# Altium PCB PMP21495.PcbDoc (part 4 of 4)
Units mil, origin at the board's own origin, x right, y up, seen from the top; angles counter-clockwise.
Board outline 10700 x 5800 mil, 6 copper layers (Top Layer, Signal Layer 3, Signal Layer 1, Signal Layer 2, Signal Layer 4, Bottom Layer), stack 66 mil thick; 305 components, 138 nets, 864 pads, 367 vias.
Unrouted connection lines stored in the file: 2.
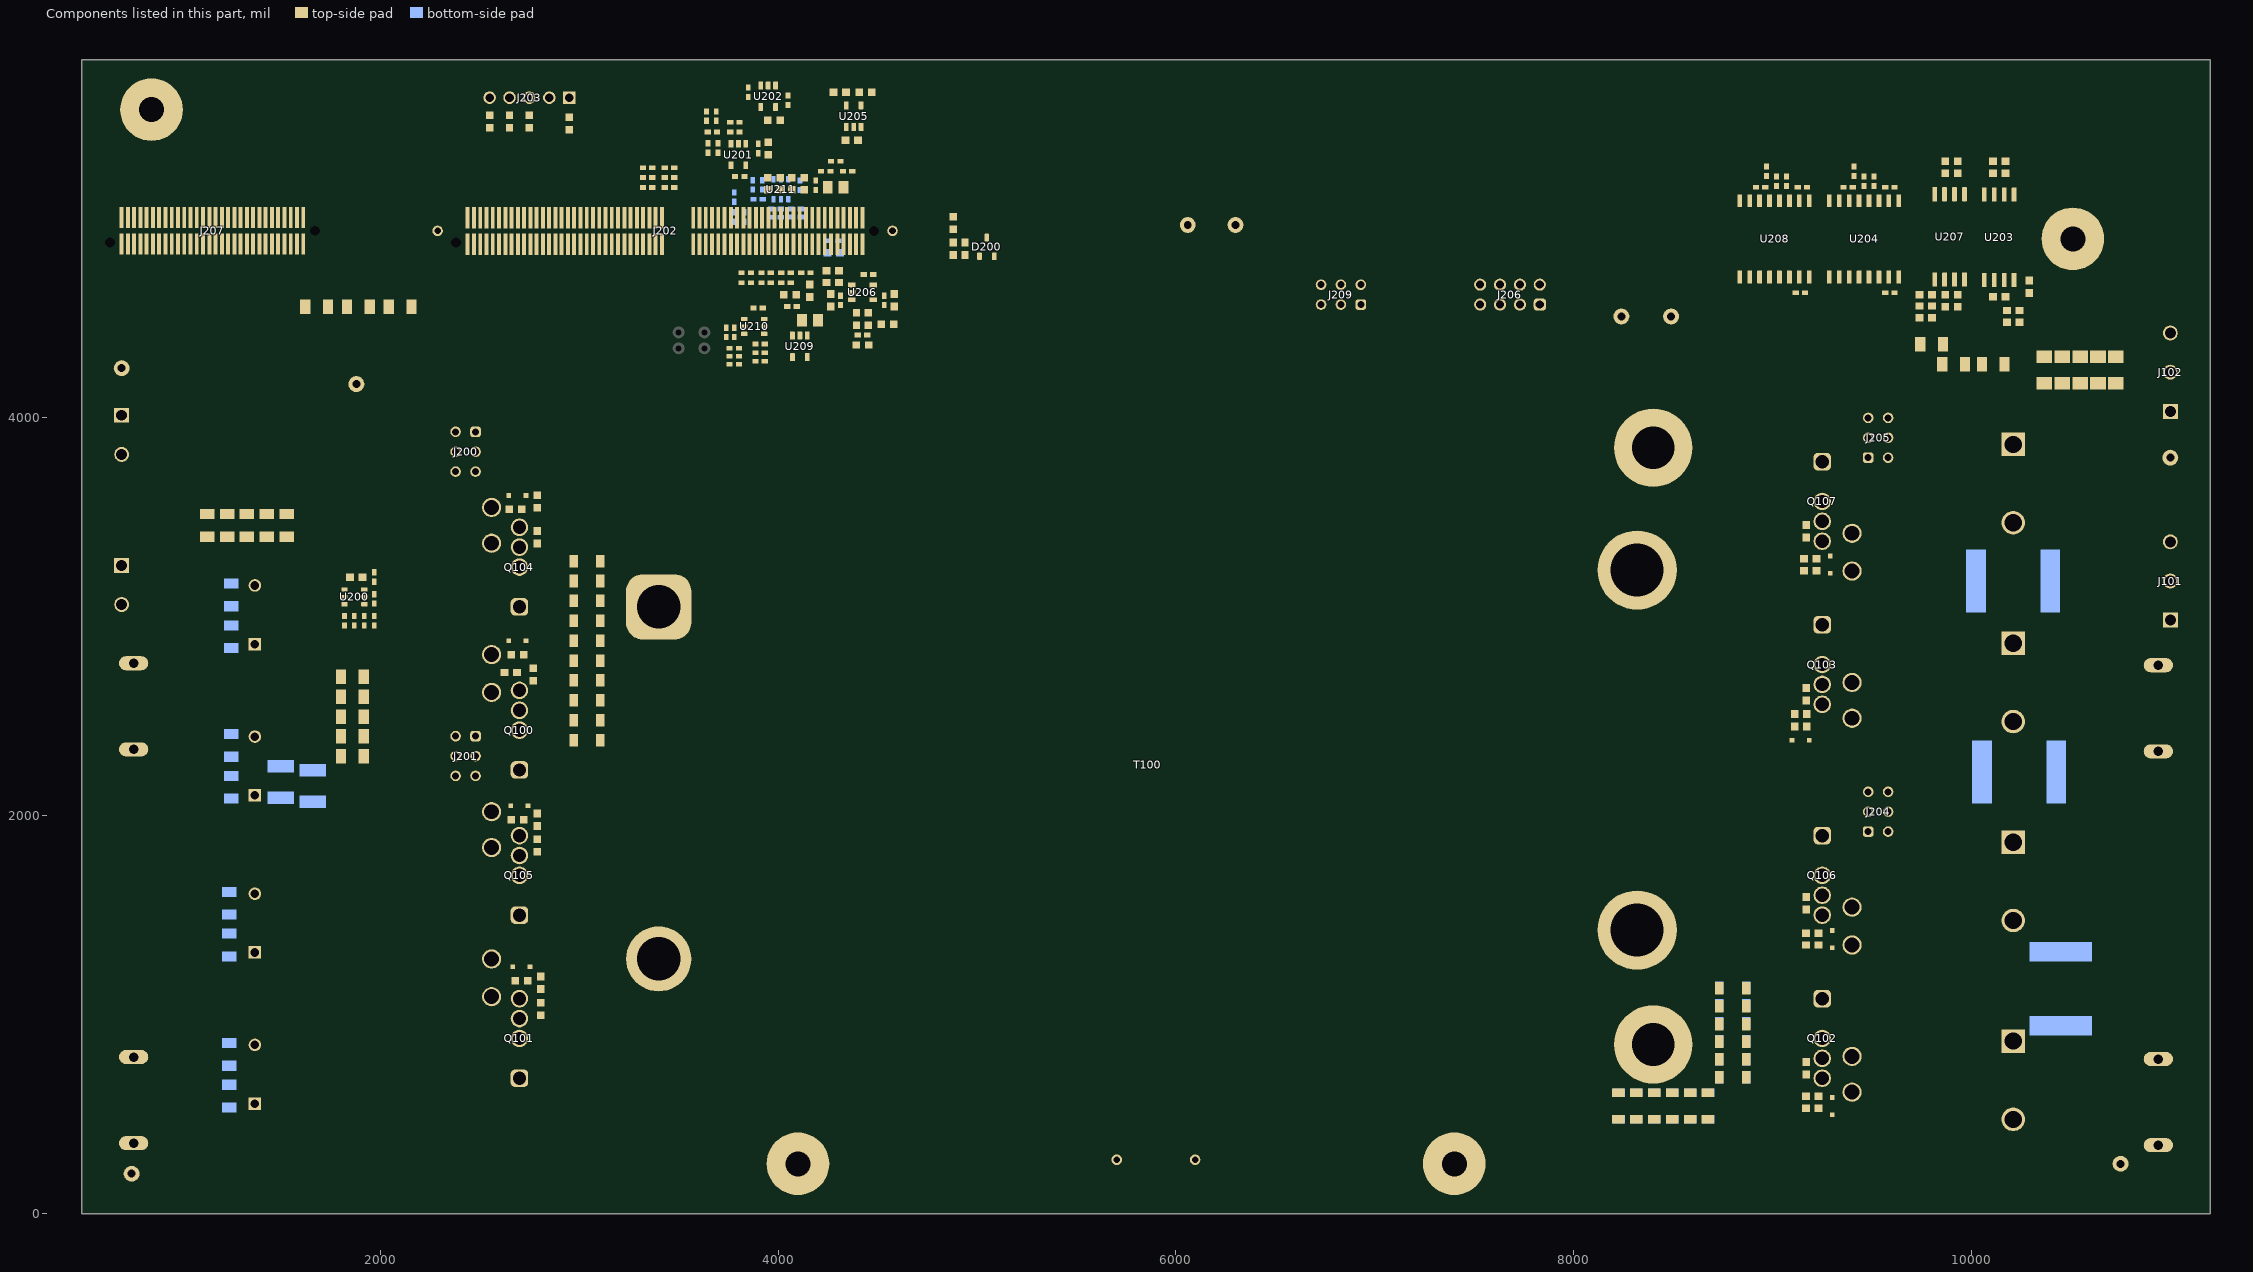
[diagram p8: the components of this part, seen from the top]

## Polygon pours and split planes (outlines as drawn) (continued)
SGND on Signal Layer 2 "SGND" (solid, pour order 309): 6090,500 6070,480 6070,30 6090,10 6340,10 10480,10 10500,30 10500,390 10310,580 9560,580 9560,500
PGND on Signal Layer 2 "PGND" (solid, pour order 320): 22 vertices, not listed, extent 510,2140 11190,5790
NetC100_2 on Signal Layer 3 "C100_2" (solid, pour order 342): 8120,580 8100,600 8100,1120 8648.66,1120 8648.66,1190 8742.6,1190 8760,1172.6 8760,620 8720,580
NetJ105_1 on Signal Layer 3 "J105_1" (solid, pour order 330): 19 vertices, not listed, extent 8100,2720 9320,4060
PGND on Signal Layer 3 "PGND" (solid, pour order 297): 1830,1910 2320,1420 2320,1090 2910,500 5710,500 5730,480 5730,30 5710,10 1610,10 1480,140 1480,1910
PGND on Signal Layer 3 "PGND" (solid, pour order 293): 1080,3430 1020,3370 1020,3340 1020,1560 1070,1510 1470,1510 1830,1870 1830,2850 1590,3090 1590,3410 1570,3430
PGND on Signal Layer 3 "PGND" (solid, pour order 286): 22 vertices, not listed, extent 510,2140 11190,5790
BATT_RTN on Signal Layer 3 "BATT_RTN" (solid, pour order 283): 10320,4270 10300,4290 10300,4450 10410,4560 11170,4560 11190,4540 11190,3960 11170,3940 10961.89,3940 10810,4091.89 10810,4220 10760,4270
VBATT on Signal Layer 3 "VBATT" (solid, pour order 279): 11020,2230 11070,2280 11070,3440 11040,3470 10920,3470 10760,3310 10760,2280 10810,2230
VBUS on Signal Layer 3 "VBUS" (solid, pour order 272): 620,3310 650,3340 860,3340 890,3310 890,2780 890,2320 860,2290 650,2290 620,2320
NetC100_1 on Signal Layer 3 "C100_1" (solid, pour order 263): 29 vertices, not listed, extent 8100,200 9310,1980
NetC103_1 on Signal Layer 3 "C103_1" (solid, pour order 251): 9600,2340 9810,2130 9810,2560 9600,2770
NetC103_1 on Signal Layer 3 "C103_1" (solid, pour order 250): 41 vertices, not listed, extent 9190,190 11070,3940
SGND on Signal Layer 3 "SGND" (solid, pour order 303): 25 vertices, not listed, extent 9500,360 11060,4210
SGND on Signal Layer 3 "SGND" (solid, pour order 304): 20 vertices, not listed, extent 7460,1840 10400,4770
SGND on Signal Layer 3 "SGND" (solid, pour order 306): 6090,500 6070,480 6070,30 6090,10 6340,10 10480,10 10500,30 10500,390 10310,580 9560,580 9560,500
NetC100_2 on Signal Layer 1 "C100_2" (solid, pour order 340): 8120,580 8100,600 8100,1120 8648.66,1120 8648.66,1190 8742.6,1190 8760,1172.6 8760,620 8720,580
NetJ105_1 on Signal Layer 1 "J105_1" (solid, pour order 328): 19 vertices, not listed, extent 8100,2720 9320,4060
PGND on Signal Layer 1 "PGND" (solid, pour order 318): 22 vertices, not listed, extent 510,2140 11190,5790
PGND on Signal Layer 1 "PGND" (solid, pour order 314): 1830,1910 2320,1420 2320,1090 2910,500 5710,500 5730,480 5730,30 5710,10 1610,10 1480,140 1480,1910
5Vs on Signal Layer 1 "5Vs" (solid, pour order 271): 49 vertices, not listed, extent 7500,2000 10270,4780
5Vp on Signal Layer 1 "5Vp" (solid, pour order 276): 27 vertices, not listed, extent 2320,2180 6970,4640
PGND on Signal Layer 1 "PGND" (solid, pour order 292): 1080,3430 1020,3370 1020,3340 1020,1560 1070,1510 1470,1510 1830,1870 1830,2850 1590,3090 1590,3410 1570,3430
SGND on Signal Layer 1 "SGND" (solid, pour order 281): 33 vertices, not listed, extent 9200,360 11060,4210
VBATT on Signal Layer 1 "VBATT" (solid, pour order 278): 11020,2230 11070,2280 11070,3440 11040,3470 10920,3470 10760,3310 10760,2280 10810,2230
VBUS on Signal Layer 1 "VBUS" (solid, pour order 270): 620,3310 650,3340 860,3340 890,3310 890,2780 890,2320 860,2290 650,2290 620,2320
NetC100_1 on Signal Layer 1 "C100_1" (solid, pour order 256): 29 vertices, not listed, extent 8100,200 9310,1980
SGND on Signal Layer 1 "SGND" (solid, pour order 302): 20 vertices, not listed, extent 7460,1840 10400,4770
SGND on Signal Layer 1 "SGND" (solid, pour order 307): 6090,500 6070,480 6070,30 6090,10 6340,10 10480,10 10500,30 10500,390 10310,580 9560,580 9560,500

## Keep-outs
Keep-Out Layer:
  text ".Layer_Name" at 577,-858.49 h60

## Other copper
Top Layer:
  text ".Layer_Name" at 577,-858.49 h60
Bottom Layer:
  text ".Layer_Name" at 577,-858.49 h60

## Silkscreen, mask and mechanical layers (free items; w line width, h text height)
Top Overlay:
  region: 2680,210 2380,210 2380,110 2680,110
  lines w7: 2560,1000 2230,1000 2230,2500 2560,2500 2560,2100 ; 2560,2530 2230,2530 2230,4030 2560,4030 2560,3640 ; 8100,520 3648.66,520 3648.66,4120 8100,4120 ; 8648.66,1120 8648.66,3620 ; 9400,480 9730,480 9730,2230 9400,2230 9400,1660 ; 9400,2340 9730,2340 9730,4090 9400,4090 9400,3530
  lines w10: 960,3290 960,3750 1120,3910 1220,3910 ; 1040,3970 1220,3970 ; 2630,3470 2640,3470 2660,3490 2660,3500 ; 3230,4240 3530,4240 3600,4310 ; 3230,4460 3380,4460 3460,4380 ; 3230,4560 3380,4560 3470,4470 ; 3230,4660 3390,4660 3590,4460 ; 3550,5400 3600,5400 ; 4400,5170 4470,5170 ; 4640,4510 4660,4490 5160,4490 ; 5300,4760 6140,4760 6190,4710 6190,4390 5950,4150 5270,4150 5210,4150 5160,4200 5160,4710 5210,4760 5310,4760 ; 8100,520 8100,1120 8648.66,1120 ; 8100,4120 8100,3620 8648.66,3620 ; 9370,5200 9340,5230 9340,5430 9380,5470 ; 9570,4495 9665,4495 9680,4510 ; 10050,4560 10050,4600 10060,4610 ; 3130,5370 3160,5340 3550,5340 3550,5510 3340,5720 3160,5720 3130,5690 3130,5370 ; 4470,5120 4470,5310 4510,5350 4530,5370 5060,5370 5060,5180 5000,5120 4470,5120 ; 9280,4400 9300,4380 9360,4380 9510,4380 9570,4440 9570,4550 9550,4570 9300,4570 9280,4550 9280,4520 9280,4400
  text "PGND" at 5980,5070 h72.83
  text "5Vp" at 6240,5060 h72.83
  text "Coil_Sec_N" at 2650,4630 h60
  text "-" at 11100,4620 h150
  text "5Vs" at 8180,4600 h72.83
  text "SGND" at 8410,4600 h72.83
  text "Coil_Pri_N" at 2650,4530 h60
  text "Coil_Pri_P" at 2650,4430 h60
  text "Coil_Sec_P" at 2650,4220 h60
  text "-" at 540,4130 h150
  text "V1: 400V-600V DC / Power Max 7kW" at 1250,3870 h100
  text "+" at 11110,3510.04 h150
  text "+" at 540,3380 h150
  text "V2 / 250-450V DC / Pmax 6.6kW" at 10780,2810 h100 r90
  text "Fuse F30AL650V / Installed between XF100 & XF101" at 640,1930 h100 r270
  text "Fuse F30AL650V / Installed between XF102 & XF103" at 11060,1240 h100 r90
  text "PMP21495 RevB" at 1600,120 h108.27
  text ".Layer_Name" at 577,-858.49 h60
  text "Fuse F30AL650V / Installed between XF100 & XF101" at 3950,-2600 h100 r270
  text "Fuse F30AL650V / Installed between XF100 & XF101" at -5650,-2780 h100 r270
Bottom Overlay:
  lines w7.01: 2500,3574.8 1608.82,3574.8 1608.82,2925.2 2711.18,2925.2 ; 2701.18,545.2 1598.82,545.2 1598.82,1194.8 2701.18,1194.8 ; 2711.18,1375.2 1608.82,1375.2 1608.82,2024.8 2711.18,2024.8 ; 2711.18,2105.2 1608.82,2105.2 1608.82,2754.8 2711.18,2754.8 ; 9248.82,555.2 10351.18,555.2 10351.18,1204.8 9248.82,1204.8 ; 9248.82,1375.2 10351.18,1375.2 10351.18,2024.8 9248.82,2024.8 ; 9248.82,2435.2 10351.18,2435.2 10351.18,3084.8 9248.82,3084.8 ; 9248.82,3255.2 10351.18,3255.2 10351.18,3904.8 9248.82,3904.8
  lines w10: 4170,5170 4210,5210 4550,5210 ; 4550,5100 4550,5420 4580,5450 5010,5450 5050,5410 5050,5110 5010,5070 4580,5070 4550,5100
  text ".Layer_Name" at 577,-858.49 h60
Top Paste:
  text ".Layer_Name" at 577,-858.49 h60
Bottom Paste:
  text ".Layer_Name" at 577,-858.49 h60
Top Solder:
  rectangle: 3170,2820 3647.01,3270
  rectangle: 3130,1010 3620,1510
  text ".Layer_Name" at 577,-858.49 h60
  text ".Layer_Name" at 577,-858.49 h60
Bottom Solder:
  rectangle: 9800,1900 10040,2870
  rectangle: 2870,690 3030,2010
  text ".Layer_Name" at 577,-858.49 h60
Drill Guide:
  text ".Layer_Name" at 577,-858.49 h60
M1 Board Outline:
  the board outline again, w10
  text ".Layer_Name" at 577,-858.49 h60
M2 Board Dimensions:
  rectangle: 0,-275 125,-150
  rectangle: 125,-400 500,-275
  lines w7: 0,-275 1000,-275 ; 125,-400 125,-150 ; 250,-400 250,-150 ; 500,-400 500,-150 ; 750,-400 750,-150 ; 0,-400 1000,-400 1000,-150 0,-150 0,-400
  text ".Layer_Name" at 577,-858.49 h60
M3 3D STEP Top:
  text ".Layer_Name" at 577,-858.49 h60
M4 3D STEP Bottom:
  text ".Layer_Name" at 577,-858.49 h60
M5 Assembly Top:
  lines w10: -292,-930.17 6308,-930.17 ; -292,-726.83 6310,-726.83 ; -292,-523.5 -292,-1133.5 3713,-1133.5 6310,-1133.5 6310,-523.5 -291.5,-523.5 -291.5,-1133.5 1284,-1133.5 ; 2173,-1133.5 2173,-523.5 ; 3440,-726.83 3440,-523.5 ; 4280,-726.83 4280,-523.5 ; 4902,-1140 4902,-937.17
  text "COMPONENTS MARKED 'DNP' SHOULD NOT BE POPULATED." at 1153.5,-318.5 h60
  text "ASSEMBLY VARIANT:" at 1153,-434 h60
  text ".VariantName" at 2189,-434 h60
  text "PCB VIEWED FROM TOP SIDE" at -228.5,-655.67 h60
  text "BOARD #:" at 2248,-655.67 h60
  text ".PRJ_Number" at 2793.5,-655.67 h60
  text "REV:" at 3638,-655.67 h60
  text ".PCB_Rev" at 3929.5,-655.67 h60
  text "SVN REV:" at 4476,-655.67 h60
  text ".VersionControl_RevNumber" at 4982,-655.67 h60
  text "TID #:" at 2248,-859 h60
  text ".TID" at 2793.5,-859 h60
  text "PLOT NAME =" at -228.5,-1064.34 h60
  text ".plot_File_Name" at 577,-1064.34 h60
  text "GENERATED    :" at 2250,-1064.34 h60
  text ".Print_Date" at 3119.5,-1064.34 h60
  text ".Print_Time" at 3848.5,-1064.34 h60
  text "TEXAS INSTRUMENTS" at 5113,-1064.34 h60
M6 Assembly Bottom:
  lines w10: -292.5,-727.33 6309.5,-727.33 ; -290.5,-930.67 6309.5,-930.67 ; 1115.5,-1140.5 1115.5,-937.67 ; 1737.5,-727.33 1737.5,-524 ; 2577.5,-727.33 2577.5,-524 ; 3844.5,-1134 3844.5,-524 ; 4733.5,-1134 6309,-1134 6309,-524 -292.5,-524 -292.5,-1134 2304.5,-1134 6309.5,-1134 6309.5,-524
  text "COMPONENTS MARKED 'DNP' SHOULD NOT BE POPULATED." at 6102,-318 h60
  text ".VariantName" at 5058,-434 h60
  text "ASSEMBLY VARIANT:" at 6097,-434 h60
  text ".VersionControl_RevNumber" at 1035.5,-656.17 h60
  text "SVN REV:" at 1541.5,-656.17 h60
  text ".PCB_Rev" at 2088,-656.17 h60
  text "REV:" at 2379.5,-656.17 h60
  text ".PRJ_Number" at 3224,-656.17 h60
  text "BOARD #:" at 3769.5,-656.17 h60
  text "PCB VIEWED FROM BOTTOM SIDE" at 6246,-656.17 h60
  text ".TID" at 3224,-859.5 h60
  text "TID #:" at 3769.5,-859.5 h60
  text "TEXAS INSTRUMENTS" at 904.5,-1064.84 h60
  text ".Print_Time" at 2169,-1064.84 h60
  text ".Print_Date" at 2898,-1064.84 h60
  text "GENERATED    :" at 3767.5,-1064.84 h60
  text ".plot_File_Name" at 5440.5,-1064.84 h60
  text "PLOT NAME =" at 6246,-1064.84 h60
M9 Title Sheet:
  drawing of 57 lines, arcs and shapes, not listed
  text "1" at 739.84,8036.5 h70
  text "2" at 3235.5,8036.5 h70
  text "3" at 5724.84,8036.5 h70
  text "4" at 8231.51,8036.5 h70
  text "5" at 10730.5,8036.5 h70
  text "6" at 13235.5,8036.5 h70
  text "A" at -416.5,6893.5 h70
  text "A" at 14383.5,6893.5 h70
  text "B" at -416.5,4513.5 h70
  text "B" at 14383.5,4513.5 h70
  text "C" at -416.5,2138.5 h70
  text "C" at 14383.5,2138.5 h70
  text "PROJECT TITLE:" at 11343.5,277.5 h45
  text ".PRJ_Title" at 11393.5,144.17 h70
  text "DESIGNED FOR:" at 11343.5,-23.5 h45
  text ".PRJ_Customer" at 11393.5,-163.5 h70
  text "D" at -416.5,-231.5 h70
  text "D" at 14383.5,-231.5 h70
  text "FILE NAME:" at 11343.5,-323.5 h45
  text ".PCB_File_Name_No_Path" at 11393.5,-443.5 h70
  text "Texas Instruments (TI) and/or its licensors do not warrant the accuracy or completeness of this specification" at 6374,-605.34 h45
  text "ENGINEER:" at 11343.5,-613.5 h45
  text "LAYOUT BY:" at 12848.5,-613.5 h45
  text "or any information contained therein. TI and/or its licensors do not warrant that this design will meet" at 6329.01,-718 h45
  text ".PRJ_Engineer" at 11393.5,-768.49 h70
  text ".PCB_Layout" at 12899,-768.49 h70
  text "the specifications, will be suitable for your application or fit for any particular purpose, or will operate in" at 6329.01,-830.67 h45
  text ".Layer_Name" at 577,-858.49 h60
  text "ALTIUM DESIGNER VERSION:" at 12848.5,-923.5 h45
  text "an implementation. TI and/or its licensors do not warrant that the design is production worthy. You should" at 6329.01,-943.33 h45
  text "completely validate and test your design implementation to confirm the system functionality for your application." at 6374,-1056 h45
  text ".print_Scale" at 11393.5,-1056.83 h70
  text ".Application_BuildNumber" at 12899,-1056.83 h70
  text "1" at 739.84,-1263.5 h70
  text "2" at 3235.5,-1263.5 h70
  text "3" at 5724.84,-1263.5 h70
  text "4" at 8231.51,-1263.5 h70
  text "5" at 10730.5,-1263.5 h70
  text "6" at 13235.5,-1263.5 h70
M10 Fab Notes:
  drawing of 189 lines, arcs and shapes, not listed
  text "DESIGN INFORMATION" at 12382.02,6356.17 h60
  text "MIN. TRACK WIDTH:" at 11737.46,6224.05 h60
  text "8" at 12833.7,6224.05 h60
  text "MIL" at 12988.46,6224.05 h60
  text "MIN. CLEARANCE:" at 11737.46,6099.92 h60
  text "0.2" at 12773.7,6099.93 h60
  text "mm" at 12988.46,6099.92 h60
  text "MIN. VIA PAD SIZE:" at 11737.46,5975.8 h60
  text "20" at 12803.71,5975.8 h60
  text "MIL" at 12988.46,5975.8 h60
  text "0.05mm (2MIL)" at 12432.46,5845.9 h60
  text "MINIMUM ANNULAR RING" at 11408.23,5837.67 h60
  text "EXTERNAL" at 13140.46,5837.67 h60
  text "PER" at 11608.23,5727.55 h60
  text "IPC-D-275 CLASS 2 LEVEL C" at 11828.23,5727.54 h60
  text "MIL, HOLES" at 13316.46,5627.07 h60
  text "+/-" at 12924,5618.48 h60
  text "+/-" at 13778,5618.48 h60
  text "REGISTRATION TOLERANCES:" at 11408.23,5617.42 h60
  text "METAL" at 12608,5617.42 h60
  text "5" at 13184.2,5617.42 h60
  text "3" at 14017.2,5617.42 h60
  text "MIL" at 14133.46,5617.42 h60
  text "HOLE SIZE TOLERANCE (UNLESS OTHERWISE SPECIFIED):" at 11408.23,5519.1 h60
  text "+/-" at 13778,5516.23 h60
  text "3" at 14017.2,5515.17 h60
  text "MIL" at 14133.46,5515.17 h60
  text "MATERIAL:" at 11333.46,5377.52 h60
  text "FR-4 High Tg" at 12319.9,5249 h60
  text "X" at 12175.46,5241.01 h60
  text "FR-408" at 11754.46,5236.49 h60
  text "OTHER" at 13242.46,5236.49 h60
  text "62 MIL (1.6mm) +/-10%" at 12074.56,5093.46 h60
  text "X" at 11954.46,5091.01 h60
  text "THICKNESS:" at 11408.23,5085.24 h60
  text "OTHER" at 13359.46,5085.24 h60
  text "TOLERANCE:" at 11408.23,4946.92 h60
  text "X" at 12256.46,4946.92 h60
  text "ANSI IPC-6012 TYPE 3 CLASS 2" at 12434.48,4946.92 h60
  text "OTHER +/-" at 12434.46,4802.73 h60
  text "BOW & TWIST:" at 11408.23,4657.54 h60
  text "X" at 12256.46,4657.54 h60
  text "ANSI IPC-6012 TYPE 3 CLASS 2" at 12434.48,4657.54 h60
  text "OTHER +/-" at 12434.46,4510.85 h60
  text "DRILLING:" at 11333.46,4380.23 h60
  text "NC_DRILL FILES" at 13094.46,4275.04 h60
  text "REFERENCE:" at 11408.23,4271.1 h60
  text "X" at 12065.46,4271.01 h60
  text "AS SHOWN" at 12243.46,4271.1 h60
  text "X" at 12966.46,4271.1 h60
  text "OTHER" at 13392.46,4128.85 h60
  text "PTH COPPER THICKNESS:" at 11407.91,4125.32 h60
  text "X" at 12547.14,4125.32 h60
  text "20-30 um" at 12675.14,4125.32 h60
  text "BOARD FINISH:" at 11333.46,3977.73 h60
  text "SILKSCREEN:" at 11488.68,3867.6 h60
  text "X" at 12446.46,3867.6 h60
  text "TOP" at 12563.46,3867.6 h60
  text "X" at 12956.46,3867.6 h60
  text "BOTTOM" at 13074.46,3867.6 h60
  text "SILKSCREEN COLOR:" at 11488.68,3712.41 h60
  text "X" at 12445.46,3712.41 h60
  text "WHITE" at 12563.46,3712.41 h60
  text "OTHER" at 13074.46,3712.41 h60
  text "X" at 12576.46,3568.96 h60
  text "GREEN" at 12694.46,3568.96 h60
  text "OTHER" at 13312.46,3568.96 h60
  text "SOLDER RESIST COLOR:" at 11488.68,3562.1 h60
  text "X" at 12576.46,3414.71 h60
  text "MATTE" at 12694.46,3414.71 h60
  text "SEMI-GLOSS" at 13312,3414.07 h60
  text "IMMERSION GOLD (ENIG)" at 12394.46,3241.94 h60
  text "ENEPIG" at 13732,3234.72 h60
  text "SURFACE FINISH:" at 11333.46,3233.72 h60
  text "X" at 12216.46,3233.72 h60
  text "IMM. TIN/SILVER OR EQUIV" at 11663,3096.4 h60
  text "OTHER" at 13094.46,3092.47 h60
  text "ARRAY/PANEL:" at 11333.46,2937.09 h60
  text "CUT AND TRIM PER M1 BOARD OUTLINE" at 12394.46,2928.87 h60
  text "N.C. ROUTE" at 12394.46,2792.9 h60
  text "X" at 13082.46,2792.9 h60
  text "V. SCORE" at 13260.46,2792.9 h60
  text "CERTIFICATION:" at 11333.46,2663.77 h60
  text "MATERIALS AND WORKMANSHIP FOR ALL PCBS" at 12058.46,2663.77 h60
  text "TO MEET OR EXCEED THE REQUIREMENTS OF:" at 12058.46,2569.71 h60
  text "X" at 11695.97,2441.08 h60
  text "ANSI IPC-A-600F CLASS ->" at 11823.96,2441.08 h60
  text "X" at 13471.97,2441.08 h60
  text "2" at 13581.96,2441.08 h60
  text "1" at 13266.96,2439.58 h60
  text "3" at 13935.96,2439.58 h60
  text "X" at 12507.97,2293.39 h60
  text "RoHS" at 12635.96,2293.39 h60
  text "OTHER" at 13280.36,2293.39 h60
  text "PER ORDER" at 13677.42,2293.39 h60
  text "ALL BOARDS MUST MEET OR EXCEED UL94-V0 REQUIREMENTS." at 11361,2139.57 h60
  text "PCB MUST BEAR THE UL94V-0 UL REGISTERED MATERIAL ID NUMBER" at 11361,2023.5 h60
  text "ADDITIONAL REQUIREMENTS:" at 11333.46,1854.08 h60
  text "MICROSECTION:" at 11408.23,1746.95 h60
  text "YES" at 12313.96,1746.95 h60
  text "REQUIRED" at 13175.46,1602.62 h60
  text "BARE BOARD ELEC. TEST:" at 11408.23,1599.76 h60
  text "NONE" at 12713.96,1599.76 h60
  text "X" at 13057.46,1599.76 h60
  text "PER ORDER" at 13767.46,1599.76 h60
  text "XX MIL VIAS REQUIRE NON-CONDUCTIVE FILL AND PLANARIZE" at 11576.38,1394.82 h59
  text "XX MIL VIAS REQUIRE CONDUCTIVE FILL AND PLANARIZE" at 11584.38,1290.84 h60
  text "OUTER XX MIL TRACES REQUIRE 50 OHM SINGLE-ENDED IMPEDANCE" at 11583.39,1127.46 h58
  text "LAYER 2 & 3 (INNER LAYERS) XX MIL WIDE, XX MIL SPACE / TRACES REQUIRE 100 OHM DIFFERENTIAL IMPEDANCE" at 11575.39,891.74 h60
  text ".Layer_Name" at 577,-858.49 h60
M11 Gerber Information:
  lines w10: -292,-930.17 6308,-930.17 ; -292,-726.83 6310,-726.83 ; -292,-523.5 -292,-1133.5 3713,-1133.5 6310,-1133.5 6310,-523.5 -291.5,-523.5 -291.5,-1133.5 1284,-1133.5 ; 2173,-1133.5 2173,-523.5 ; 3440,-726.83 3440,-523.5 ; 4280,-726.83 4280,-523.5 ; 4902,-1140 4902,-937.17
  text "ALL ARTWORK VIEWED FROM TOP SIDE" at -228.5,-655.67 h60
  text "BOARD #:" at 2248,-655.67 h60
  text ".PRJ_Number" at 2793.5,-655.67 h60
  text "REV:" at 3638,-655.67 h60
  text ".PCB_Rev" at 3929.5,-655.67 h60
  text "SVN REV:" at 4476,-655.67 h60
  text ".VersionControl_RevNumber" at 4982,-655.67 h60
  text "LAYER NAME =" at -228.5,-858.49 h60
  text "TID #:" at 2248,-859 h60
  text ".TID" at 2793.5,-859 h60
  text "PLOT NAME =" at -228.5,-1064.34 h60
  text ".plot_File_Name" at 577,-1064.34 h60
  text "GENERATED    :" at 2250,-1064.34 h60
  text ".Print_Date" at 3119.5,-1064.34 h60
  text ".Print_Time" at 3848.5,-1064.34 h60
  text "TEXAS INSTRUMENTS" at 5113,-1064.34 h60
M12 Stackup:
  drawing of 399 lines, arcs and shapes, not listed
  text "Layer" at 6700,7770 h60
  text "Name" at 7109.91,7770 h60
  text "Material" at 8049.65,7770 h60
  text "Thickness" at 8909.42,7770 h60
  text "Constant" at 9559.26,7770 h60
  text "Board Layer Stack" at 10129.12,7770 h60
  text "1" at 6700,7650 h60
  text "Top Overlay" at 7109.91,7650 h60
  text "2" at 6700,7530 h60
  text "Top Solder" at 7109.91,7530 h60
  text "Solder Resist" at 8049.65,7530 h60
  text "0.40mil" at 8909.42,7530 h60
  text "3.5" at 9559.26,7530 h60
  text "3" at 6700,7410 h60
  text "Top Layer" at 7109.91,7410 h60
  text "Copper" at 8049.65,7410 h60
  text "4.20mil" at 8909.42,7410 h60
  text "4" at 6700,7290 h60
  text "Dielectric1" at 7109.91,7290 h60
  text "8.00mil" at 8909.42,7290 h60
  text "4.2" at 9559.26,7290 h60
  text "5" at 6700,7170 h60
  text "Signal Layer 3" at 7109.91,7170 h60
  text "Copper" at 8049.65,7170 h60
  text "1.40mil" at 8909.42,7170 h60
  text "6" at 6700,7050 h60
  text "Dielectric 4" at 7109.91,7050 h60
  text "FR-4" at 8049.65,7050 h60
  text "14.00mil" at 8909.42,7050 h60
  text "4.2" at 9559.26,7050 h60
  text "7" at 6700,6930 h60
  text "Signal Layer 1" at 7109.91,6930 h60
  text "Copper" at 8049.65,6930 h60
  text "1.40mil" at 8909.42,6930 h60
  text "8" at 6700,6810 h60
  text "Dielectric 2" at 7109.91,6810 h60
  text "8.00mil" at 8909.42,6810 h60
  text "4.2" at 9559.26,6810 h60
  text "9" at 6700,6690 h60
  text "Signal Layer 2" at 7109.91,6690 h60
  text "Copper" at 8049.65,6690 h60
  text "1.40mil" at 8909.42,6690 h60
  text "10" at 6700,6570 h60
  text "Dielectric 5" at 7109.91,6570 h60
  text "FR-4" at 8049.65,6570 h60
  text "14.00mil" at 8909.42,6570 h60
  text "4.2" at 9559.26,6570 h60
  text "11" at 6700,6450 h60
  text "Signal Layer 4" at 7109.91,6450 h60
  text "Copper" at 8049.65,6450 h60
  text "1.40mil" at 8909.42,6450 h60
  text "12" at 6700,6330 h60
  text "Dielectric 3" at 7109.91,6330 h60
  text "8.00mil" at 8909.42,6330 h60
  text "4.2" at 9559.26,6330 h60
  text "13" at 6700,6210 h60
  text "Bottom Layer" at 7109.91,6210 h60
  text "Copper" at 8049.65,6210 h60
  text "4.20mil" at 8909.42,6210 h60
  text "14" at 6700,6090 h60
  text "Bottom Solder" at 7109.91,6090 h60
  text "Solder Resist" at 8049.65,6090 h60
  text "0.40mil" at 8909.42,6090 h60
  text "3.5" at 9559.26,6090 h60
  text "15" at 6700,5970 h60
  text "Bottom Overlay" at 7109.91,5970 h60
  text ".Layer_Name" at 577,-858.49 h60
M13 Component Bodies Top:
  text ".Layer_Name" at 577,-858.49 h60
M14 Component Bodies Bottom:
  text ".Layer_Name" at 577,-858.49 h60
M15 Courtyards Top:
  text ".Layer_Name" at 577,-858.49 h60
M16 Courtyards Bottom:
  text ".Layer_Name" at 577,-858.49 h60
Drill Drawing:
  drawing of 191 lines, arcs and shapes, not listed
  text "Symbol" at 600.63,7988.89 h49.98
  text "Count" at 961.6,7988.89 h49.98
  text "Hole Size" at 1384.14,7988.89 h49.98
  text "Plated" at 2195.32,7988.89 h49.98
  text "Hole Type" at 2556.3,7988.89 h49.98
  text "Drill Layer Pair" at 3075.51,7988.89 h49.98
  text "Via/Pad" at 4122.65,7988.89 h49.98
  text "Pad Shape" at 4541.92,7988.89 h49.98
  text "Template" at 5069.46,7988.89 h49.98
  text "Description" at 5950.04,7988.89 h49.98
  text "Hole Tolerance (+)" at 6552.52,7988.89 h49.98
  text "Hole Tolerance (-)" at 7488.13,7988.89 h49.98
  text "Hole Length" at 8423.74,7988.89 h49.98
  text "Routed Path Length" at 9193.28,7988.89 h49.98
  text "2" at 961.6,7884.76 h41.65
  text "33.07mil (0.840mm)" at 1384.14,7884.76 h41.65
  text "PTH" at 2195.32,7884.76 h41.65
  text "Round" at 2556.3,7884.76 h41.65
  text "Top Layer - Bottom Layer" at 3075.51,7884.76 h41.65
  text "Pad" at 4122.65,7884.76 h41.65
  text "Rounded" at 4541.92,7884.76 h41.65
  text "c135h84" at 5069.46,7884.76 h41.65
  text "-" at 8423.74,7884.76 h41.65
  text "-" at 9193.28,7884.76 h41.65
  text "2" at 961.6,7780.63 h41.65
  text "33.47mil (0.850mm)" at 1384.14,7780.63 h41.65
  text "PTH" at 2195.32,7780.63 h41.65
  text "Round" at 2556.3,7780.63 h41.65
  text "Top Layer - Bottom Layer" at 3075.51,7780.63 h41.65
  text "Pad" at 4122.65,7780.63 h41.65
  text "Rounded" at 4541.92,7780.63 h41.65
  text "c135h85" at 5069.46,7780.63 h41.65
  text "-" at 8423.74,7780.63 h41.65
  text "-" at 9193.28,7780.63 h41.65
  text "2" at 961.6,7676.49 h41.65
  text "214.57mil (5.450mm)" at 1384.14,7676.49 h41.65
  text "PTH" at 2195.32,7676.49 h41.65
  text "Round" at 2556.3,7676.49 h41.65
  text "Top Layer - Bottom Layer" at 3075.51,7676.49 h41.65
  text "Pad" at 4122.65,7676.49 h41.65
  text "Rounded" at 4541.92,7676.49 h41.65
  text "c1000h545" at 5069.46,7676.49 h41.65
  text "-" at 8423.74,7676.49 h41.65
  text "-" at 9193.28,7676.49 h41.65
  text "2" at 961.6,7572.36 h41.65
  text "218.50mil (5.550mm)" at 1384.14,7572.36 h41.65
  text "PTH" at 2195.32,7572.36 h41.65
  text "Round" at 2556.3,7572.36 h41.65
  text "Top Layer - Bottom Layer" at 3075.51,7572.36 h41.65
  text "Pad" at 4122.65,7572.36 h41.65
  text "(Mixed)" at 4541.92,7572.36 h41.65
  text "(Mixed)" at 5069.46,7572.36 h41.65
  text "-" at 8423.74,7572.36 h41.65
  text "-" at 9193.28,7572.36 h41.65
  text "2" at 961.6,7468.22 h41.65
  text "265.75mil (6.750mm)" at 1384.14,7468.22 h41.65
  text "PTH" at 2195.32,7468.22 h41.65
  text "Round" at 2556.3,7468.22 h41.65
  text "Top Layer - Bottom Layer" at 3075.51,7468.22 h41.65
  text "Pad" at 4122.65,7468.22 h41.65
  text "Rounded" at 4541.92,7468.22 h41.65
  text "c1012h675" at 5069.46,7468.22 h41.65
  text "-" at 8423.74,7468.22 h41.65
  text "-" at 9193.28,7468.22 h41.65
  text "4" at 961.6,7364.09 h41.65
  text "30.00mil (0.762mm)" at 1384.14,7364.09 h41.65
  text "PTH" at 2195.32,7364.09 h41.65
  text "Round" at 2556.3,7364.09 h41.65
  text "Top Layer - Bottom Layer" at 3075.51,7364.09 h41.65
  text "Pad" at 4122.65,7364.09 h41.65
  text "Rounded" at 4541.92,7364.09 h41.65
  text "c152h76" at 5069.46,7364.09 h41.65
  text "-" at 8423.74,7364.09 h41.65
  text "-" at 9193.28,7364.09 h41.65
  text "C" at 578.33,7354.1 h46.28
  text "4" at 961.6,7259.96 h41.65
  text "50.00mil (1.270mm)" at 1384.14,7259.96 h41.65
  text "NPTH" at 2195.32,7259.96 h41.65
  text "Round" at 2556.3,7259.96 h41.65
  text "Top Layer - Bottom Layer" at 3075.51,7259.96 h41.65
  text "Pad" at 4122.65,7259.96 h41.65
  text "Rounded" at 4541.92,7259.96 h41.65
  text "c3hn127m90" at 5069.46,7259.96 h41.65
  text "-" at 8423.74,7259.96 h41.65
  text "-" at 9193.28,7259.96 h41.65
  text "4" at 961.6,7155.82 h41.65
  text "125.98mil (3.200mm)" at 1384.14,7155.82 h41.65
  text "PTH" at 2195.32,7155.82 h41.65
  text "Round" at 2556.3,7155.82 h41.65
  text "Top Layer - Bottom Layer" at 3075.51,7155.82 h41.65
  text "Pad" at 4122.65,7155.82 h41.65
  text "Rounded" at 4541.92,7155.82 h41.65
  text "c800h320" at 5069.46,7155.82 h41.65
  text "-" at 8423.74,7155.82 h41.65
  text "-" at 9193.28,7155.82 h41.65
  text "B" at 578.33,7145.83 h46.28
  text "8" at 961.6,7051.69 h41.65
  text "40.95mil (1.040mm)" at 1384.14,7051.69 h41.65
  text "PTH" at 2195.32,7051.69 h41.65
  text "Round" at 2556.3,7051.69 h41.65
  text "Top Layer - Bottom Layer" at 3075.51,7051.69 h41.65
  text "Pad" at 4122.65,7051.69 h41.65
  text "(Mixed)" at 4541.92,7051.69 h41.65
  text "(Mixed)" at 5069.46,7051.69 h41.65
  text "-" at 8423.74,7051.69 h41.65
  text "-" at 9193.28,7051.69 h41.65
  text "A" at 578.33,7041.7 h46.28
  text "8" at 961.6,6947.56 h41.65
  text "47.24mil (1.200mm)" at 1384.14,6947.56 h41.65
  text "PTH" at 2195.32,6947.56 h41.65
  text "Slot" at 2556.3,6947.56 h41.65
  text "Top Layer - Bottom Layer" at 3075.51,6947.56 h41.65
  text "Pad" at 4122.65,6947.56 h41.65
  text "Rounded" at 4541.92,6947.56 h41.65
  text "r180_375h120_250r100" at 5069.46,6947.56 h41.65
  text "98.43mil (2.500mm)" at 8423.74,6947.56 h41.65
  text "51.18mil (1.300mm)" at 9193.28,6947.56 h41.65
  text "8" at 961.6,6843.42 h41.65
  text "86.61mil (2.200mm)" at 1384.14,6843.42 h41.65
  text "PTH" at 2195.32,6843.42 h41.65
  text "Round" at 2556.3,6843.42 h41.65
  text "Top Layer - Bottom Layer" at 3075.51,6843.42 h41.65
  text "Pad" at 4122.65,6843.42 h41.65
  text "(Mixed)" at 4541.92,6843.42 h41.65
  text "(Mixed)" at 5069.46,6843.42 h41.65
  text "-" at 8423.74,6843.42 h41.65
  text "-" at 9193.28,6843.42 h41.65
  text "9" at 961.6,6739.29 h41.65
  text "40.00mil (1.016mm)" at 1384.14,6739.29 h41.65
  text "PTH" at 2195.32,6739.29 h41.65
  text "Round" at 2556.3,6739.29 h41.65
  text "Top Layer - Bottom Layer" at 3075.51,6739.29 h41.65
  text "Pad" at 4122.65,6739.29 h41.65
  text "Rounded" at 4541.92,6739.29 h41.65
  text "c203h102" at 5069.46,6739.29 h41.65
  text "-" at 8423.74,6739.29 h41.65
  text "-" at 9193.28,6739.29 h41.65
  text "10" at 961.6,6635.15 h41.65
  text "55.12mil (1.400mm)" at 1384.14,6635.15 h41.65
  text "PTH" at 2195.32,6635.15 h41.65
  text "Round" at 2556.3,6635.15 h41.65
  text "Top Layer - Bottom Layer" at 3075.51,6635.15 h41.65
  text "Pad" at 4122.65,6635.15 h41.65
  text "(Mixed)" at 4541.92,6635.15 h41.65
  text "(Mixed)" at 5069.46,6635.15 h41.65
  text "-" at 8423.74,6635.15 h41.65
  text "-" at 9193.28,6635.15 h41.65
  text "13" at 961.6,6531.02 h41.65
  text "43.31mil (1.100mm)" at 1384.14,6531.02 h41.65
  text "PTH" at 2195.32,6531.02 h41.65
  text "Round" at 2556.3,6531.02 h41.65
  text "Top Layer - Bottom Layer" at 3075.51,6531.02 h41.65
  text "Pad" at 4122.65,6531.02 h41.65
  text "(Mixed)" at 4541.92,6531.02 h41.65
  text "(Mixed)" at 5069.46,6531.02 h41.65
  text "-" at 8423.74,6531.02 h41.65
  text "-" at 9193.28,6531.02 h41.65
  text "16" at 961.6,6426.89 h41.65
  text "75.00mil (1.905mm)" at 1384.14,6426.89 h41.65
  text "PTH" at 2195.32,6426.89 h41.65
  text "Round" at 2556.3,6426.89 h41.65
  text "Top Layer - Bottom Layer" at 3075.51,6426.89 h41.65
  text "Pad" at 4122.65,6426.89 h41.65
  text "Rounded" at 4541.92,6426.89 h41.65
  text "c245h190" at 5069.46,6426.89 h41.65
  text "-" at 8423.74,6426.89 h41.65
  text "-" at 9193.28,6426.89 h41.65
  text "30" at 961.6,6322.75 h41.65
  text "35.43mil (0.900mm)" at 1384.14,6322.75 h41.65
  text "PTH" at 2195.32,6322.75 h41.65
  text "Round" at 2556.3,6322.75 h41.65
  text "Top Layer - Bottom Layer" at 3075.51,6322.75 h41.65
  text "Pad" at 4122.65,6322.75 h41.65
  text "(Mixed)" at 4541.92,6322.75 h41.65
  text "(Mixed)" at 5069.46,6322.75 h41.65
  text "3.15mil (0.080mm)" at 6552.52,6322.75 h41.65
  text "3.15mil (0.080mm)" at 7488.13,6322.75 h41.65
  text "-" at 8423.74,6322.75 h41.65
  text "-" at 9193.28,6322.75 h41.65
  text "32" at 961.6,6218.62 h41.65
  text "66.93mil (1.700mm)" at 1384.14,6218.62 h41.65
  text "PTH" at 2195.32,6218.62 h41.65
  text "Round" at 2556.3,6218.62 h41.65
  text "Top Layer - Bottom Layer" at 3075.51,6218.62 h41.65
  text "Pad" at 4122.65,6218.62 h41.65
  text "(Mixed)" at 4541.92,6218.62 h41.65
  text "(Mixed)" at 5069.46,6218.62 h41.65
  text "-" at 8423.74,6218.62 h41.65
  text "-" at 9193.28,6218.62 h41.65
  text "367" at 961.6,6114.49 h41.65
  text "10.00mil (0.254mm)" at 1384.14,6114.49 h41.65
  text "PTH" at 2195.32,6114.49 h41.65
  text "Round" at 2556.3,6114.49 h41.65
  text "Top Layer - Bottom Layer" at 3075.51,6114.49 h41.65
  text "Via" at 4122.65,6114.49 h41.65
  text "Rounded" at 4541.92,6114.49 h41.65
  text "v51h25" at 5069.46,6114.49 h41.65
  text "-" at 8423.74,6114.49 h41.65
  text "-" at 9193.28,6114.49 h41.65
  text "523 Total" at 961.6,6010.35 h41.65
  text "Slot definitions :" at 600.63,5903.59 h41.65
  text "Routed Path Length" at 1326.11,5903.59 h41.65
  text "= Calculated from tool start centre position to tool end centre position." at 2100.17,5903.59 h41.65
  text "Hole Length" at 1326.11,5828.07 h41.65
  text "= Routed Path Length + Tool Size = Slot length as defined in the PCB layout" at 1815.63,5828.07 h41.65
  text ".Layer_Name" at 577,-858.49 h60
M17 Embedded Cavity:
  text ".Layer_Name" at 577,-858.49 h60
M18 Embedded Assembly:
  text ".Layer_Name" at 577,-858.49 h60
M19 Embedded Keepout:
  text ".Layer_Name" at 577,-858.49 h60

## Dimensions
500,0 to 500,5800 on M2 Board Dimensions
500,0 to 11200,0 on M2 Board Dimensions
0,-400 to 1000,-400 on M2 Board Dimensions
